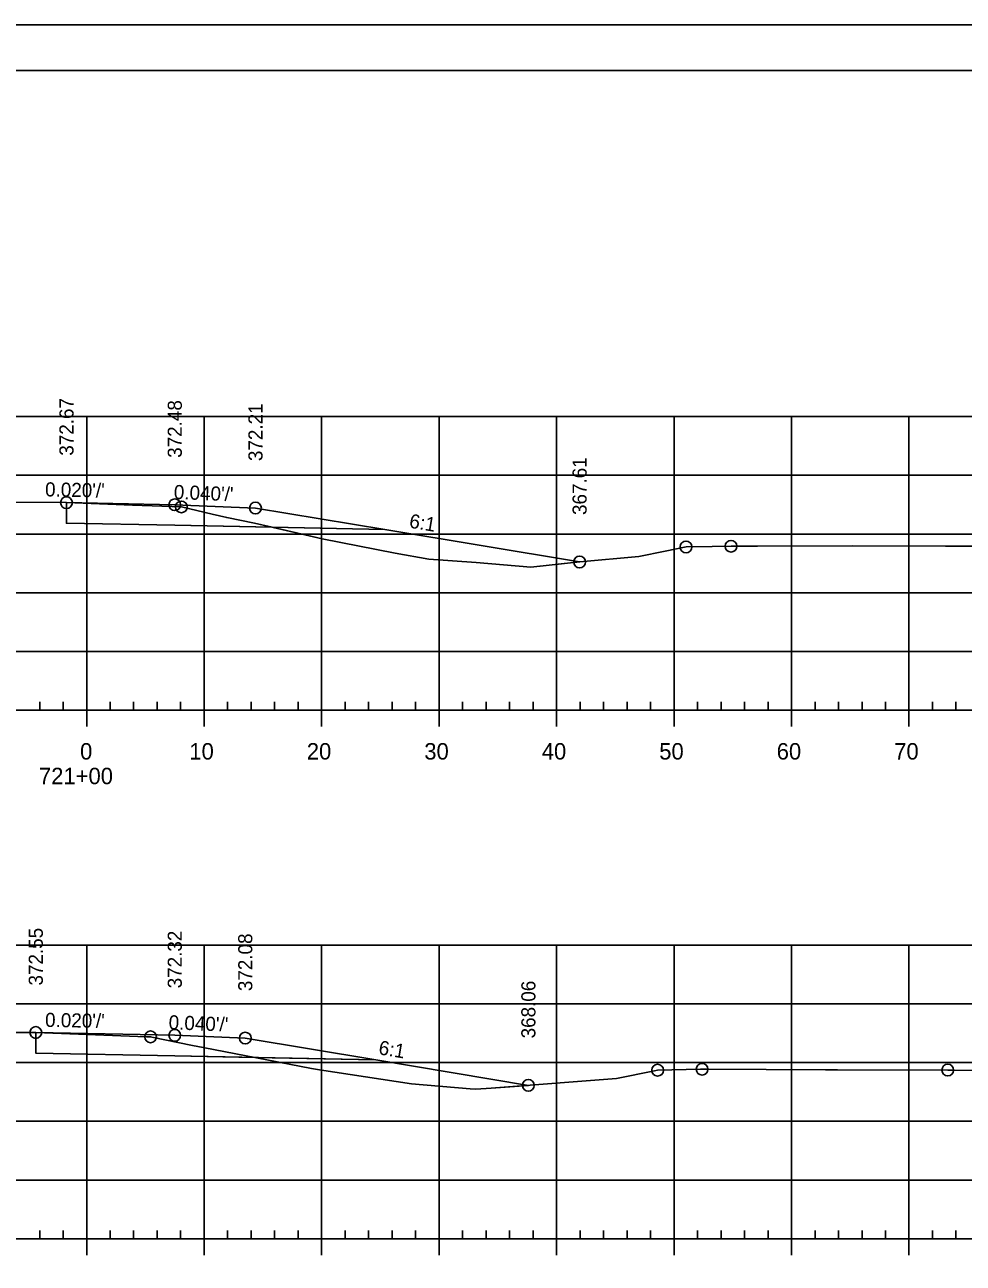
# Model space of a CAD drawing. Extents: x 1359801 to 1362404, y 372415 to 374228.
# Drawn here: x 1360582.3 to 1360662.1, y 373909.2 to 374014.6 of the extents above; entities that cross this region are included whole.
import ezdxf

# ---------------------------------------------------------------- set-up
doc = ezdxf.new("R2010")
doc.units = 0
for name, color, linetype in [('S_DRG_PT_SYM', 7, 'Continuous'), ('S_ELECTRIC_UTILITIES_ANNOT', 7, 'Continuous'), ('S_IRON_PIN', 7, 'Continuous'), ('S_MAILBOX', 7, 'Continuous'), ('S_PRIMARY_CTL', 7, 'Continuous'), ('S_SANITARY_SEWER', 7, 'Continuous'), ('S_SHOULDER', 7, 'Continuous'), ('S_UNDERGROUND_CABLE', 7, 'Continuous'), ('S_UTL_PT_SYM', 7, 'Continuous'), ('S_WATER_UTILITIES', 7, 'Continuous')]:
    doc.layers.add(name, color=color, linetype=linetype)

msp = doc.modelspace()

# ---------------------------------------------------------------- linework, layer by layer
at = {"layer": 'S_DRG_PT_SYM'}
for points in [[(1360571.23, 373974), (1360585.81, 373973.94), (1360591.42, 373973.74), (1360595.59, 373973.58), (1360598.21, 373972.97), (1360599.45, 373972.67), (1360601.82, 373972.19), (1360607.58, 373970.87), (1360613.78, 373969.64), (1360616.65, 373969.13), (1360620.68, 373968.85), (1360625.35, 373968.45), (1360629.52, 373968.89), (1360634.53, 373969.35), (1360636.78, 373969.82), (1360638.55, 373970.17), (1360640.77, 373970.21), (1360642.38, 373970.23), (1360644.64, 373970.24), (1360652.72, 373970.26), (1360660.64, 373970.25), (1360663.26, 373970.24)], [(1360580.84, 373928.83), (1360583.2, 373928.83), (1360592.62, 373928.47), (1360592.97, 373928.46), (1360593.09, 373928.43), (1360596.54, 373927.72), (1360597.46, 373927.55), (1360606.66, 373925.77), (1360607.35, 373925.66), (1360615.17, 373924.46), (1360620.17, 373924.04), (1360620.66, 373924), (1360621.97, 373924.09), (1360632.63, 373924.91), (1360635.87, 373925.57), (1360636.13, 373925.62), (1360639.79, 373925.7), (1360639.92, 373925.7), (1360640.33, 373925.7), (1360650.41, 373925.65), (1360651.44, 373925.65), (1360660.83, 373925.63), (1360661.25, 373925.62), (1360664.1, 373925.58)]]:
    msp.add_lwpolyline(points, dxfattribs=at)
at = {"layer": 'S_ELECTRIC_UTILITIES_ANNOT'}
for p, q in [((1360603.33, 373971.84), (1360601.82, 373972.19)), ((1360612.9, 373971.65), (1360603.33, 373971.84)), ((1360603.33, 373971.84), (1360607.58, 373970.87)), ((1360629.49, 373968.89), (1360612.9, 373971.65)), ((1360601.84, 373926.7), (1360597.46, 373927.55)), ((1360612.14, 373926.5), (1360601.84, 373926.7)), ((1360601.84, 373926.7), (1360606.66, 373925.77)), ((1360625.13, 373924.33), (1360612.14, 373926.5))]:
    msp.add_line(p, q, dxfattribs=at)
for points in [[(1360601.82, 373972.19), (1360599.45, 373972.67), (1360598.21, 373972.97), (1360595.59, 373973.58), (1360591.42, 373973.74), (1360585.81, 373973.94)], [(1360585.81, 373973.94), (1360585.81, 373972.19), (1360595.03, 373972.01), (1360603.33, 373971.84)], [(1360607.58, 373970.87), (1360613.78, 373969.64), (1360616.65, 373969.13), (1360620.68, 373968.85), (1360625.35, 373968.45), (1360629.49, 373968.89)], [(1360597.46, 373927.55), (1360596.54, 373927.72), (1360593.09, 373928.43), (1360592.97, 373928.46), (1360592.62, 373928.47), (1360583.2, 373928.83)], [(1360583.2, 373928.83), (1360583.2, 373927.08), (1360595.03, 373926.84), (1360601.84, 373926.7)], [(1360606.66, 373925.77), (1360607.35, 373925.66), (1360615.17, 373924.46), (1360620.17, 373924.04), (1360620.66, 373924), (1360621.97, 373924.09), (1360625.13, 373924.33)]]:
    msp.add_lwpolyline(points, dxfattribs=at)
at = {"layer": 'S_MAILBOX'}
for p, q in [((1360442.53, 373981.27), (1360732.53, 373981.27)), ((1360587.53, 373956.27), (1360587.53, 373981.27)), ((1360597.53, 373956.27), (1360597.53, 373981.27)), ((1360607.53, 373956.27), (1360607.53, 373981.27)), ((1360617.53, 373956.27), (1360617.53, 373981.27)), ((1360627.53, 373956.27), (1360627.53, 373981.27)), ((1360637.53, 373956.27), (1360637.53, 373981.27)), ((1360647.53, 373956.27), (1360647.53, 373981.27)), ((1360657.53, 373956.27), (1360657.53, 373981.27)), ((1360442.53, 373976.27), (1360732.53, 373976.27)), ((1360442.53, 373971.27), (1360732.53, 373971.27)), ((1360442.53, 373966.27), (1360732.53, 373966.27)), ((1360442.53, 373961.27), (1360732.53, 373961.27)), ((1360442.53, 373956.27), (1360732.53, 373956.27)), ((1360442.53, 373936.27), (1360732.53, 373936.27)), ((1360587.53, 373911.27), (1360587.53, 373936.27)), ((1360597.53, 373911.27), (1360597.53, 373936.27)), ((1360607.53, 373911.27), (1360607.53, 373936.27)), ((1360617.53, 373911.27), (1360617.53, 373936.27)), ((1360627.53, 373911.27), (1360627.53, 373936.27)), ((1360637.53, 373911.27), (1360637.53, 373936.27)), ((1360647.53, 373911.27), (1360647.53, 373936.27)), ((1360657.53, 373911.27), (1360657.53, 373936.27)), ((1360442.53, 373931.27), (1360732.53, 373931.27)), ((1360442.53, 373926.27), (1360732.53, 373926.27)), ((1360442.53, 373921.27), (1360732.53, 373921.27)), ((1360442.53, 373916.27), (1360732.53, 373916.27)), ((1360442.53, 373911.27), (1360732.53, 373911.27))]:
    msp.add_line(p, q, dxfattribs=at)
at = {"layer": 'S_SANITARY_SEWER'}
for points in [[(1360585.81, 373973.94), (1360595.03, 373973.76), (1360601.9, 373973.48), (1360612.9, 373971.65), (1360629.49, 373968.89)], [(1360583.2, 373928.83), (1360595.03, 373928.59), (1360601.03, 373928.35), (1360612.14, 373926.5), (1360625.13, 373924.33)]]:
    msp.add_lwpolyline(points, dxfattribs=at)
at = {"layer": 'S_SHOULDER'}
msp.add_line((1360417.13, 374014.63), (1360750.46, 374014.63), dxfattribs=at)
for points in [[(1360417.12, 374014.63), (1360750.46, 374014.63), (1360750.46, 373801.29), (1360417.12, 373801.29)], [(1360663.45, 374010.73), (1360663.45, 374000.85), (1360699.18, 374000.85), (1360699.18, 373997.93), (1360722.38, 373997.93), (1360722.38, 373973.6), (1360745.71, 373973.6), (1360745.71, 373805.27), (1360429.53, 373805.27), (1360429.53, 374010.73)]]:
    msp.add_lwpolyline(points, close=True, dxfattribs=at)
for centre in [(1360585.81, 373973.94), (1360595.03, 373973.76), (1360595.59, 373973.58), (1360601.9, 373973.48), (1360638.55, 373970.17), (1360642.38, 373970.23), (1360629.49, 373968.89), (1360583.2, 373928.83), (1360592.97, 373928.46), (1360595.03, 373928.59), (1360601.03, 373928.35), (1360636.13, 373925.62), (1360639.92, 373925.7), (1360660.83, 373925.63), (1360625.13, 373924.33)]:
    msp.add_circle(centre, 0.5, dxfattribs=at)
at = {"layer": 'S_UNDERGROUND_CABLE'}
for points in [[(1360585.81, 373973.94), (1360585.81, 373972.19), (1360585.81, 373972.19), (1360595.03, 373972.01), (1360612.9, 373971.65)], [(1360583.2, 373928.83), (1360583.2, 373927.08), (1360583.2, 373927.08), (1360595.03, 373926.84), (1360612.14, 373926.5)]]:
    msp.add_lwpolyline(points, dxfattribs=at)
at = {"layer": 'S_UTL_PT_SYM'}
msp.add_line((1360429.53, 374010.73), (1360745.71, 374010.73), dxfattribs=at)
at = {"layer": 'S_WATER_UTILITIES'}
for p, q in [((1360583.53, 373956.27), (1360583.53, 373956.97)), ((1360585.53, 373956.27), (1360585.53, 373956.97)), ((1360589.53, 373956.27), (1360589.53, 373956.97)), ((1360591.53, 373956.27), (1360591.53, 373956.97)), ((1360593.53, 373956.27), (1360593.53, 373956.97)), ((1360595.53, 373956.27), (1360595.53, 373956.97)), ((1360599.53, 373956.27), (1360599.53, 373956.97)), ((1360601.53, 373956.27), (1360601.53, 373956.97)), ((1360603.53, 373956.27), (1360603.53, 373956.97)), ((1360605.53, 373956.27), (1360605.53, 373956.97)), ((1360609.53, 373956.27), (1360609.53, 373956.97)), ((1360611.53, 373956.27), (1360611.53, 373956.97)), ((1360613.53, 373956.27), (1360613.53, 373956.97)), ((1360615.53, 373956.27), (1360615.53, 373956.97)), ((1360619.53, 373956.27), (1360619.53, 373956.97)), ((1360621.53, 373956.27), (1360621.53, 373956.97)), ((1360623.53, 373956.27), (1360623.53, 373956.97)), ((1360625.53, 373956.27), (1360625.53, 373956.97)), ((1360629.53, 373956.27), (1360629.53, 373956.97)), ((1360631.53, 373956.27), (1360631.53, 373956.97)), ((1360633.53, 373956.27), (1360633.53, 373956.97)), ((1360635.53, 373956.27), (1360635.53, 373956.97)), ((1360639.53, 373956.27), (1360639.53, 373956.97)), ((1360641.53, 373956.27), (1360641.53, 373956.97)), ((1360643.53, 373956.27), (1360643.53, 373956.97)), ((1360645.53, 373956.27), (1360645.53, 373956.97)), ((1360649.53, 373956.27), (1360649.53, 373956.97)), ((1360651.53, 373956.27), (1360651.53, 373956.97)), ((1360653.53, 373956.27), (1360653.53, 373956.97)), ((1360655.53, 373956.27), (1360655.53, 373956.97)), ((1360659.53, 373956.27), (1360659.53, 373956.97)), ((1360661.53, 373956.27), (1360661.53, 373956.97)), ((1360442.53, 373956.27), (1360732.53, 373956.27)), ((1360587.53, 373954.87), (1360587.53, 373956.27)), ((1360597.53, 373954.87), (1360597.53, 373956.27)), ((1360607.53, 373954.87), (1360607.53, 373956.27)), ((1360617.53, 373954.87), (1360617.53, 373956.27)), ((1360627.53, 373954.87), (1360627.53, 373956.27)), ((1360637.53, 373954.87), (1360637.53, 373956.27)), ((1360647.53, 373954.87), (1360647.53, 373956.27)), ((1360657.53, 373954.87), (1360657.53, 373956.27)), ((1360583.53, 373911.27), (1360583.53, 373911.97)), ((1360585.53, 373911.27), (1360585.53, 373911.97)), ((1360589.53, 373911.27), (1360589.53, 373911.97)), ((1360591.53, 373911.27), (1360591.53, 373911.97)), ((1360593.53, 373911.27), (1360593.53, 373911.97)), ((1360595.53, 373911.27), (1360595.53, 373911.97)), ((1360599.53, 373911.27), (1360599.53, 373911.97)), ((1360601.53, 373911.27), (1360601.53, 373911.97)), ((1360603.53, 373911.27), (1360603.53, 373911.97)), ((1360605.53, 373911.27), (1360605.53, 373911.97)), ((1360609.53, 373911.27), (1360609.53, 373911.97)), ((1360611.53, 373911.27), (1360611.53, 373911.97)), ((1360613.53, 373911.27), (1360613.53, 373911.97)), ((1360615.53, 373911.27), (1360615.53, 373911.97)), ((1360619.53, 373911.27), (1360619.53, 373911.97)), ((1360621.53, 373911.27), (1360621.53, 373911.97)), ((1360623.53, 373911.27), (1360623.53, 373911.97)), ((1360625.53, 373911.27), (1360625.53, 373911.97)), ((1360629.53, 373911.27), (1360629.53, 373911.97)), ((1360631.53, 373911.27), (1360631.53, 373911.97)), ((1360633.53, 373911.27), (1360633.53, 373911.97)), ((1360635.53, 373911.27), (1360635.53, 373911.97)), ((1360639.53, 373911.27), (1360639.53, 373911.97)), ((1360641.53, 373911.27), (1360641.53, 373911.97)), ((1360643.53, 373911.27), (1360643.53, 373911.97)), ((1360645.53, 373911.27), (1360645.53, 373911.97)), ((1360649.53, 373911.27), (1360649.53, 373911.97)), ((1360651.53, 373911.27), (1360651.53, 373911.97)), ((1360653.53, 373911.27), (1360653.53, 373911.97)), ((1360655.53, 373911.27), (1360655.53, 373911.97)), ((1360659.53, 373911.27), (1360659.53, 373911.97)), ((1360661.53, 373911.27), (1360661.53, 373911.97)), ((1360442.53, 373911.27), (1360732.53, 373911.27)), ((1360587.53, 373909.87), (1360587.53, 373911.27)), ((1360597.53, 373909.87), (1360597.53, 373911.27)), ((1360607.53, 373909.87), (1360607.53, 373911.27)), ((1360617.53, 373909.87), (1360617.53, 373911.27)), ((1360627.53, 373909.87), (1360627.53, 373911.27)), ((1360637.53, 373909.87), (1360637.53, 373911.27)), ((1360647.53, 373909.87), (1360647.53, 373911.27)), ((1360657.53, 373909.87), (1360657.53, 373911.27))]:
    msp.add_line(p, q, dxfattribs=at)

# ---------------------------------------------------------------- texts
at = {"layer": 'S_IRON_PIN'}
for s, rotation, p in [('372.67', 90, (1360586.41, 373977.94)), ('372.48', 90, (1360595.63, 373977.76)), ('372.21', 90, (1360602.5, 373977.48)), ('367.61', 90, (1360630.09, 373972.89)), ("0.020'/'", 358.8542, (1360583.98, 373974.48)), ("0.040'/'", 357.7094, (1360594.93, 373974.26)), ('6:1', 350.5377, (1360614.93, 373971.82)), ('372.55', 90, (1360583.8, 373932.83)), ('372.32', 90, (1360595.63, 373932.59)), ('372.08', 90, (1360601.63, 373932.35)), ('368.06', 90, (1360625.73, 373928.33)), ("0.020'/'", 358.8542, (1360583.98, 373929.31)), ("0.040'/'", 357.7094, (1360594.49, 373929.11)), ('6:1', 350.5377, (1360612.32, 373926.98))]:
    msp.add_text(s, height=1.2, rotation=rotation, dxfattribs=at).set_placement(p)
at = {"layer": 'S_PRIMARY_CTL'}
for s, p in [('0', (1360586.97, 373952.07)), ('10', (1360596.27, 373952.07)), ('20', (1360606.27, 373952.07)), ('30', (1360616.27, 373952.07)), ('40', (1360626.27, 373952.07)), ('50', (1360636.27, 373952.07)), ('60', (1360646.27, 373952.07)), ('70', (1360656.27, 373952.07)), ('721+00', (1360583.47, 373949.97))]:
    msp.add_text(s, height=1.4, dxfattribs=at).set_placement(p)
at = {"layer": 'S_SHOULDER'}
for p in [(1360585.77, 373973.89), (1360583.15, 373928.78)]:
    msp.add_text('+', height=0.1, dxfattribs=at).set_placement(p)

doc.saveas('drawing.dxf')
